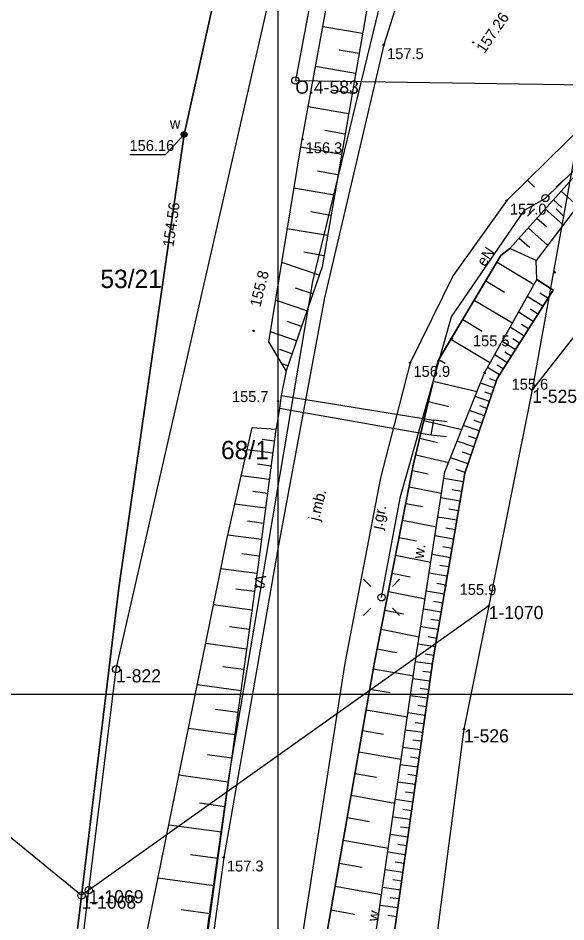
# Model space of a CAD drawing. Extents: x 5598798 to 5599616, y 5661498 to 5662453.
# Drawn here: x 5599182.2 to 5599219.7, y 5661984.4 to 5662046.3 of the extents above; entities that cross this region are included whole.
import ezdxf

# ---------------------------------------------------------------- set-up
doc = ezdxf.new("R2010")
doc.units = 0
for name, color, linetype in [('BUBZ_L_1', 7, 'Continuous'), ('BUIB_L_1', 7, 'Continuous'), ('BUIB_L_4', 7, 'Continuous'), ('Dzialki', 7, 'Continuous'), ('Kontury', 7, 'Continuous'), ('KTJZ_E_T_0', 7, 'Continuous'), ('KTJZ_L_0', 7, 'Continuous'), ('Numery_dzialek', 7, 'Continuous'), ('Numery_punktow', 7, 'Continuous'), ('Podzial_sekcyjny_krzyze', 7, 'Continuous'), ('Podzial_sekcyjny_podstawowy', 7, 'Continuous'), ('PTRW_E_T_1', 7, 'Continuous'), ('PTRW_L_0', 7, 'Continuous'), ('Punkty', 7, 'Continuous'), ('RTPW_T_0', 7, 'Continuous'), ('RTPW_T_1', 7, 'Continuous'), ('SUPE_E_T_3', 7, 'Continuous'), ('SUPE_L_3', 7, 'Continuous'), ('SUPT_E_T_0', 7, 'Continuous'), ('SUPT_L_0', 7, 'Continuous'), ('SUPW_L_0', 7, 'Continuous'), ('SUSM_T_0', 7, 'Continuous'), ('SUTW_T_0', 7, 'Continuous'), ('SUUW_E_T_5', 7, 'Continuous'), ('SUUW_T_7', 7, 'Continuous'), ('Uzytki', 7, 'Continuous')]:
    doc.layers.add(name, color=color, linetype=linetype)

# ---------------------------------------------------------------- blocks, each defined once
blk = doc.blocks.new('GRO')
blk.add_circle((0, 0), 0.045)
blk = doc.blocks.new('GRT')
blk.add_circle((0, 0), 0.25)
blk = doc.blocks.new('POINT_DISPLAY')
blk.add_line((0, 0), (0, 0))
blk = doc.blocks.new('2_RTPW01')
blk.add_circle((0, 0), 0.045)
blk = doc.blocks.new('2_RTPW02')
blk.add_circle((0, 0), 0.045)
blk = doc.blocks.new('4_SUSM01')
for p, q in [((-0.74249, 0.74249), (-1.23746, 1.23746)), ((0.74249, 0.74249), (1.23746, 1.23746)), ((-0.74249, -0.74249), (-1.23746, -1.23746)), ((0.74249, -0.74249), (1.23746, -1.23746))]:
    blk.add_line(p, q)
blk.add_circle((0, 0), 0.245)
blk = doc.blocks.new('4_SUPS01_08')
blk.add_circle((0, 0), 0.0625)
blk = doc.blocks.new('4_SUUS25')
for radius in [0.2, 0.175, 0.15, 0.125, 0.1, 0.075, 0.05, 0.025, 0.00715]:
    blk.add_circle((0, 0), radius)

msp = doc.modelspace()

# ---------------------------------------------------------------- linework, layer by layer
at = {"layer": 'BUBZ_L_1'}
for p, q in [((5599201.547205, 5662037.521709), (5599204.289076, 5662052.472617)), ((5599207.009383, 5662052.339919), (5599203.009868, 5662029.29958)), ((5599205.783558, 5662045.278206), (5599203.056496, 5662045.75159)), ((5599205.546866, 5662043.914675), (5599204.176857, 5662044.152492)), ((5599205.309049, 5662042.544666), (5599202.556014, 5662043.022559)), ((5599205.070103, 5662041.168149), (5599203.687046, 5662041.40823)), ((5599204.830022, 5662039.785092), (5599202.050766, 5662040.267536)), ((5599204.5888, 5662038.395464), (5599203.19257, 5662038.637832)), ((5599215.891937, 5662030.548676), (5599223.373416, 5662038.93789)), ((5599199.359348, 5662024.143271), (5599201.547205, 5662037.521709)), ((5599204.346432, 5662036.999235), (5599201.541391, 5662037.486155)), ((5599204.102972, 5662035.596715), (5599202.707305, 5662035.838985)), ((5599203.860701, 5662034.201048), (5599201.08301, 5662034.683221)), ((5599221.431197, 5662034.656453), (5599217.701626, 5662029.719398)), ((5599219.397499, 5662034.47957), (5599220.532764, 5662033.467144)), ((5599218.869786, 5662033.88783), (5599219.461527, 5662033.360117)), ((5599203.619615, 5662032.812202), (5599202.237557, 5662033.052111)), ((5599218.319661, 5662033.270958), (5599219.553405, 5662032.170708)), ((5599217.746172, 5662032.627887), (5599218.389243, 5662032.054398)), ((5599203.379707, 5662031.430144), (5599200.629098, 5662031.907615)), ((5599217.148327, 5662031.957504), (5599218.489092, 5662030.761813)), ((5599216.52509, 5662031.25865), (5599217.223945, 5662030.635414)), ((5599215.89, 5662030.55), (5599215.28, 5662030.07)), ((5599217.7, 5662029.72), (5599215.89, 5662030.55)), ((5599217.701626, 5662029.719398), (5599215.891937, 5662030.548676)), ((5599203.140971, 5662030.05484), (5599201.772388, 5662030.292409)), ((5599215.28, 5662030.07), (5599210.98, 5662022.88)), ((5599202.806313, 5662028.711306), (5599200.250984, 5662029.595502)), ((5599203.009868, 5662029.29958), (5599200.544989, 5662022.176077)), ((5599215.006929, 5662029.613399), (5599217.480202, 5662028.134251)), ((5599217.73, 5662028.42), (5599217.7, 5662029.72)), ((5599214.16, 5662022.02), (5599217.73, 5662028.42)), ((5599214.235444, 5662028.323406), (5599215.525438, 5662027.551921)), ((5599218.85, 5662027.7), (5599217.724991, 5662028.41102)), ((5599217.73, 5662028.42), (5599218.85, 5662027.7)), ((5599202.364215, 5662027.433642), (5599201.196884, 5662027.837562)), ((5599218.85, 5662027.7), (5599215.02, 5662021.64)), ((5599218.49449, 5662027.137496), (5599217.947415, 5662027.483254)), ((5599201.960294, 5662026.266311), (5599199.827244, 5662027.004391)), ((5599213.452142, 5662027.013652), (5599216.07165, 5662025.447048)), ((5599218.148731, 5662026.590421), (5599217.084594, 5662027.262969)), ((5599217.485406, 5662025.540878), (5599216.478847, 5662026.177037)), ((5599217.812457, 5662026.058352), (5599217.294983, 5662026.385402)), ((5599201.591254, 5662025.199786), (5599200.61683, 5662025.536957)), ((5599212.656841, 5662025.683835), (5599213.986658, 5662024.888534)), ((5599201.254084, 5662024.225362), (5599199.473529, 5662024.841471)), ((5599216.857973, 5662024.548124), (5599215.905876, 5662025.149861)), ((5599217.167327, 5662025.037598), (5599216.677852, 5662025.346953)), ((5599211.849358, 5662024.333647), (5599214.549733, 5662022.718681)), ((5599216.557104, 5662024.072075), (5599216.094113, 5662024.364691)), ((5599200.544989, 5662022.176077), (5599199.359348, 5662024.143271)), ((5599200.946029, 5662023.335085), (5599200.112645, 5662023.623453)), ((5599216.264488, 5662023.609085), (5599215.363907, 5662024.178264)), ((5599215.703115, 5662022.720855), (5599214.851262, 5662023.259238)), ((5599215.979898, 5662023.158794), (5599215.541959, 5662023.435578)), ((5599200.657661, 5662022.501701), (5599200.26733, 5662022.636764)), ((5599210.98, 5662022.88), (5599209.29, 5662015.78)), ((5599211.019573, 5662022.946169), (5599211.449659, 5662022.688954)), ((5599215.172117, 5662021.880686), (5599214.366356, 5662022.389937)), ((5599215.433924, 5662022.294929), (5599215.019681, 5662022.556736)), ((5599211.44, 5662015.25), (5599214.16, 5662022.02)), ((5599210.640276, 5662021.452758), (5599213.644769, 5662020.737604)), ((5599215.02, 5662021.64), (5599212.8, 5662015.14)), ((5599214.804276, 5662021.008376), (5599213.880341, 5662021.323936)), ((5599214.957985, 5662021.458425), (5599214.507936, 5662021.612134)), ((5599214.646496, 5662020.546408), (5599214.172294, 5662020.708367)), ((5599210.307562, 5662020.054963), (5599211.705356, 5662019.722248)), ((5599214.484538, 5662020.072206), (5599213.511017, 5662020.404701)), ((5599214.147641, 5662019.085794), (5599213.121873, 5662019.436133)), ((5599214.318291, 5662019.585446), (5599213.818639, 5662019.756096)), ((5599209.997981, 5662018.754357), (5599212.599192, 5662018.135196)), ((5599213.972471, 5662018.572911), (5599213.446005, 5662018.752719)), ((5599196.49, 5662010.61), (5599198.22, 5662018.29)), ((5599198.22, 5662018.29), (5599199.84, 5662018.16)), ((5599199.84, 5662018.16), (5599198.63, 5662008.86)), ((5599213.792663, 5662018.046445), (5599212.711845, 5662018.415585)), ((5599199.735285, 5662017.355167), (5599198.896923, 5662017.464244)), ((5599209.709925, 5662017.544183), (5599210.9201, 5662017.256127)), ((5599213.608092, 5662017.506036), (5599213.053372, 5662017.695494)), ((5599213.418634, 5662016.951316), (5599212.279812, 5662017.340267)), ((5599199.626208, 5662016.516805), (5599197.871982, 5662016.745043)), ((5599209.441898, 5662016.418152), (5599211.69396, 5662015.882098)), ((5599213.024532, 5662015.797414), (5599211.824593, 5662016.207239)), ((5599213.224158, 5662016.381905), (5599212.639667, 5662016.581531)), ((5599199.512089, 5662015.639692), (5599198.594434, 5662015.759086)), ((5599209.29, 5662015.78), (5599206.61, 5662002.2)), ((5599199.392695, 5662014.722038), (5599197.472555, 5662014.971862)), ((5599209.201512, 5662015.331619), (5599210.293462, 5662015.116124)), ((5599209.49, 5662002.77), (5599211.44, 5662015.25)), ((5599212.8, 5662015.14), (5599210.61, 5662002.29)), ((5599212.819619, 5662015.197444), (5599212.203761, 5662015.407784)), ((5599212.700862, 5662014.558302), (5599211.367431, 5662014.785556)), ((5599199.267783, 5662013.761967), (5599198.263337, 5662013.892654)), ((5599208.981634, 5662014.217459), (5599211.209954, 5662013.777703)), ((5599212.587235, 5662013.891586), (5599211.925123, 5662014.004428)), ((5599208.757283, 5662013.080637), (5599209.894105, 5662012.856287)), ((5599212.474393, 5662013.229474), (5599211.159313, 5662013.4536)), ((5599199.137097, 5662012.757521), (5599197.03535, 5662013.030974)), ((5599212.36233, 5662012.571934), (5599211.70933, 5662012.683223)), ((5599199.00037, 5662011.706648), (5599197.900923, 5662011.849694)), ((5599208.528369, 5662011.920692), (5599210.84826, 5662011.462864)), ((5599212.25104, 5662011.918934), (5599210.954059, 5662012.139976)), ((5599212.140519, 5662011.270443), (5599211.496506, 5662011.380201)), ((5599189.8, 5661977.78), (5599196.49, 5662010.61)), ((5599198.857324, 5662010.607201), (5599196.556794, 5662010.906517)), ((5599208.294799, 5662010.737153), (5599209.478338, 5662010.503583)), ((5599212.030761, 5662010.62643), (5599210.75163, 5662010.84443)), ((5599211.921761, 5662009.986865), (5599211.286612, 5662010.095112)), ((5599198.707666, 5662009.456936), (5599197.513022, 5662009.612368)), ((5599208.056478, 5662009.52954), (5599210.471703, 5662009.052898)), ((5599211.813514, 5662009.351715), (5599210.551987, 5662009.566715)), ((5599198.63, 5662008.86), (5599194.46, 5661978.54)), ((5599211.706014, 5662008.720951), (5599211.079606, 5662008.827709)), ((5599198.547876, 5662008.262875), (5599196.080851, 5662008.602173)), ((5599207.813309, 5662008.297365), (5599209.045485, 5662008.054196)), ((5599211.599257, 5662008.094543), (5599210.355091, 5662008.306584)), ((5599211.493236, 5662007.472461), (5599210.875449, 5662007.577749)), ((5599198.378227, 5662007.029363), (5599197.104972, 5662007.204477)), ((5599207.565194, 5662007.040126), (5599210.079671, 5662006.543897)), ((5599211.387948, 5662006.854673), (5599210.160906, 5662007.063796)), ((5599211.283387, 5662006.241152), (5599210.674102, 5662006.344991)), ((5599198.203112, 5662005.756108), (5599195.574556, 5662006.117621)), ((5599207.312033, 5662005.757315), (5599208.594844, 5662005.504154)), ((5599211.179548, 5662005.631867), (5599209.969392, 5662005.838111)), ((5599211.076426, 5662005.026789), (5599210.475526, 5662005.1292)), ((5599198.022356, 5662004.44183), (5599196.665733, 5662004.62841)), ((5599207.053722, 5662004.448411), (5599209.67153, 5662003.931789)), ((5599210.974015, 5662004.42589), (5599209.780515, 5662004.629296)), ((5599210.872313, 5662003.82914), (5599210.279683, 5662003.93014)), ((5599197.835775, 5662003.085207), (5599195.035112, 5662003.470391)), ((5599210.771312, 5662003.23651), (5599209.594237, 5662003.437117)), ((5599205.3, 5661973.9), (5599209.49, 5662002.77)), ((5599206.789955, 5662003.111862), (5599208.126504, 5662002.848096)), ((5599210.671009, 5662002.647973), (5599210.086535, 5662002.747583)), ((5599206.61, 5662002.2), (5599202.2, 5661977.13)), ((5599210.61, 5662002.29), (5599206.59, 5661973.92)), ((5599210.577764, 5662002.062506), (5599209.411307, 5662002.227791)), ((5599197.643184, 5662001.684875), (5599196.197734, 5662001.883672)), ((5599206.529917, 5662001.744746), (5599209.271216, 5662001.262531)), ((5599210.495121, 5662001.479277), (5599209.910912, 5662001.562059)), ((5599197.444387, 5662000.239426), (5599194.460346, 5662000.64983)), ((5599210.41234, 5662000.895068), (5599209.241954, 5662001.06091)), ((5599206.285137, 5662000.353218), (5599207.676665, 5662000.108438)), ((5599210.329418, 5662000.309875), (5599209.743241, 5662000.392936)), ((5599210.246358, 5661999.723697), (5599209.07203, 5661999.890098)), ((5599197.239185, 5661998.747405), (5599195.699093, 5661998.959219)), ((5599206.036629, 5661998.940494), (5599208.862077, 5661998.443476)), ((5599210.163157, 5661999.136534), (5599209.575005, 5661999.219874)), ((5599210.079817, 5661998.548382), (5599208.901534, 5661998.715344)), ((5599197.027371, 5661997.207314), (5599193.847947, 5661997.644589)), ((5599209.996336, 5661997.959241), (5599209.406203, 5661998.042862)), ((5599205.784334, 5661997.50625), (5599207.218578, 5661997.253956)), ((5599209.912715, 5661997.369108), (5599208.730464, 5661997.536632)), ((5599209.74505, 5661996.185863), (5599208.558817, 5661996.353951)), ((5599209.828953, 5661996.777983), (5599209.236833, 5661996.861886)), ((5599196.808733, 5661995.617601), (5599195.167802, 5661995.843284)), ((5599205.528197, 5661996.050159), (5599208.440379, 5661995.537885)), ((5599209.576821, 5661994.998632), (5599208.386593, 5661995.167286)), ((5599209.661006, 5661995.592747), (5599209.066892, 5661995.676932)), ((5599205.268158, 5661994.571888), (5599206.746429, 5661994.311849)), ((5599209.492494, 5661994.403518), (5599208.896378, 5661994.487987)), ((5599196.583051, 5661993.97667), (5599193.195451, 5661994.442577)), ((5599209.408025, 5661993.807403), (5599208.213788, 5661993.976625)), ((5599209.323414, 5661993.210285), (5599208.725291, 5661993.295038)), ((5599205.004158, 5661993.0711), (5599208.005736, 5661992.5431)), ((5599209.23866, 5661992.612162), (5599208.040401, 5661992.781954)), ((5599196.350098, 5661992.28287), (5599194.601725, 5661992.523329)), ((5599209.153764, 5661992.013032), (5599208.553627, 5661992.098071)), ((5599204.736137, 5661991.54745), (5599206.259787, 5661991.279429)), ((5599209.068725, 5661991.412895), (5599207.866431, 5661991.583259)), ((5599196.109639, 5661990.534497), (5599192.500231, 5661991.030909)), ((5599208.983543, 5661990.811747), (5599208.381385, 5661990.897073)), ((5599208.898218, 5661990.209589), (5599207.691874, 5661990.380526)), ((5599204.464033, 5661990.000592), (5599207.55775, 5661989.456384)), ((5599208.812749, 5661989.606417), (5599208.208562, 5661989.692029)), ((5599195.861433, 5661988.729793), (5599193.998583, 5661988.985996)), ((5599208.727137, 5661989.00223), (5599207.51673, 5661989.173743)), ((5599204.187784, 5661988.43017), (5599205.758205, 5661988.153922)), ((5599208.64138, 5661988.397026), (5599208.035158, 5661988.482927)), ((5599208.555479, 5661987.790805), (5599207.340995, 5661987.962896)), ((5599195.605229, 5661986.866943), (5599191.759491, 5661987.395859)), ((5599208.469433, 5661987.183563), (5599207.86117, 5661987.269753)), ((5599203.907328, 5661986.835828), (5599207.096013, 5661986.274914)), ((5599208.383243, 5661986.575299), (5599207.164669, 5661986.74797)), ((5599208.296908, 5661985.966012), (5599207.686595, 5661986.052493)), ((5599195.340771, 5661984.944074), (5599193.355949, 5661985.217053)), ((5599203.622599, 5661985.217199), (5599205.241227, 5661984.93247)), ((5599208.210427, 5661985.3557), (5599206.987749, 5661985.528952)), ((5599208.123801, 5661984.744361), (5599207.511433, 5661984.831133))]:
    msp.add_line(p, q, dxfattribs=at)
at = {"layer": 'BUIB_L_1'}
for p, q in [((5599200.544989, 5662022.176077), (5599200.203422, 5662020.477517)), ((5599200.203422, 5662020.477517), (5599200.093431, 5662019.594602)), ((5599200.093431, 5662019.594602), (5599199.865493, 5662018.178757)), ((5599210.64656, 5662018.793972), (5599210.479527, 5662017.779699)), ((5599211.579697, 5662018.675115), (5599210.64656, 5662018.793972)), ((5599210.479527, 5662017.779699), (5599211.552657, 5662017.664024))]:
    msp.add_line(p, q, dxfattribs=at)
at = {"layer": 'BUIB_L_4'}
for p, q in [((5599200.203422, 5662020.477517), (5599210.64656, 5662018.793972)), ((5599200.093431, 5662019.594602), (5599210.479527, 5662017.779699))]:
    msp.add_line(p, q, dxfattribs=at)
at = {"layer": 'Dzialki'}
for p, q in [((5599186.52, 5661986.2), (5599074.88, 5662077.34)), ((5599188.89, 5662001.71), (5599201.39, 5662056.39)), ((5599203.66, 5662055.13), (5599201.18, 5662042.06)), ((5599201.18, 5662042.06), (5599221.18, 5662041.76)), ((5599221.18, 5662041.76), (5599217.42, 5662020.87)), ((5599224.84, 5662030.32), (5599217.42, 5662020.87)), ((5599217.42, 5662020.87), (5599214.44, 5662006.05)), ((5599214.44, 5662006.05), (5599187.02, 5661986.57)), ((5599214.44, 5662006.05), (5599212.74, 5661997.6)), ((5599187.02, 5661986.57), (5599188.89, 5662001.71)), ((5599212.74, 5661997.6), (5599207.78, 5661959.89)), ((5599183.8, 5661960.37), (5599187.02, 5661986.57)), ((5599187.02, 5661986.57), (5599186.52, 5661986.2))]:
    msp.add_line(p, q, dxfattribs=at)
at = {"layer": 'Kontury'}
for p, q in [((5599186.52, 5661986.2), (5599074.88, 5662077.34)), ((5599224.84, 5662030.32), (5599217.42, 5662020.87)), ((5599217.42, 5662020.87), (5599214.44, 5662006.05)), ((5599214.44, 5662006.05), (5599212.74, 5661997.6)), ((5599212.74, 5661997.6), (5599207.78, 5661959.89)), ((5599183.8, 5661960.37), (5599187.02, 5661986.57)), ((5599187.02, 5661986.57), (5599186.52, 5661986.2))]:
    msp.add_line(p, q, dxfattribs=at)
at = {"layer": 'KTJZ_L_0'}
for p, q in [((5599208.94, 5662049.84), (5599207.24, 5662044.5)), ((5599207.24, 5662044.5), (5599203.19, 5662027.17)), ((5599221.36, 5662039.44), (5599215.67, 5662033.84)), ((5599215.89, 5662030.55), (5599223.37, 5662038.94)), ((5599215.67, 5662033.84), (5599211.99, 5662028.71)), ((5599215.28, 5662030.07), (5599215.89, 5662030.55)), ((5599210.98, 5662022.88), (5599215.28, 5662030.07)), ((5599211.99, 5662028.71), (5599209.05, 5662022.72)), ((5599203.19, 5662027.17), (5599199.97, 5662009.96)), ((5599209.05, 5662022.72), (5599207.01, 5662014.82)), ((5599209.29, 5662015.78), (5599210.98, 5662022.88)), ((5599206.61, 5662002.2), (5599209.29, 5662015.78)), ((5599207.01, 5662014.82), (5599204.57, 5662002.13)), ((5599199.97, 5662009.96), (5599196.27, 5661988.82)), ((5599204.57, 5662002.13), (5599201.57, 5661982.98)), ((5599202.2, 5661977.13), (5599206.61, 5662002.2)), ((5599196.27, 5661988.82), (5599193.67, 5661969.75))]:
    msp.add_line(p, q, dxfattribs=at)
at = {"layer": 'Podzial_sekcyjny_krzyze'}
for p, q in [((5599200, 5661997.5), (5599200, 5662002.5)), ((5599197.5, 5662000), (5599202.5, 5662000))]:
    msp.add_line(p, q, dxfattribs=at)
at = {"layer": 'Podzial_sekcyjny_podstawowy'}
for p, q in [((5599200, 5662000), (5599200, 5662250)), ((5598800, 5662000), (5599200, 5662000)), ((5599200, 5661750), (5599200, 5662000)), ((5599200, 5662000), (5599600, 5662000))]:
    msp.add_line(p, q, dxfattribs=at)
at = {"layer": 'PTRW_L_0'}
for p, q in [((5599215.89, 5662030.55), (5599215.28, 5662030.07)), ((5599217.7, 5662029.72), (5599215.89, 5662030.55)), ((5599215.28, 5662030.07), (5599210.98, 5662022.88)), ((5599217.73, 5662028.42), (5599217.7, 5662029.72)), ((5599218.85, 5662027.7), (5599217.73, 5662028.42)), ((5599215.02, 5662021.64), (5599218.85, 5662027.7)), ((5599210.98, 5662022.88), (5599209.29, 5662015.78)), ((5599212.8, 5662015.14), (5599215.02, 5662021.64)), ((5599209.29, 5662015.78), (5599206.61, 5662002.2)), ((5599210.61, 5662002.29), (5599212.8, 5662015.14)), ((5599206.61, 5662002.2), (5599202.2, 5661977.13)), ((5599206.59, 5661973.92), (5599210.61, 5662002.29))]:
    msp.add_line(p, q, dxfattribs=at)
at = {"layer": 'SUPE_L_3'}
for p, q in [((5599218.324532, 5662034.005569), (5599224.255584, 5662039.803043)), ((5599216.902559, 5662033.182877), (5599218.324532, 5662034.005569)), ((5599211.896469, 5662025.8657), (5599216.902559, 5662033.182877)), ((5599208.384646, 5662013.550115), (5599211.896469, 5662025.8657)), ((5599207.091102, 5662006.637471), (5599208.384646, 5662013.550115))]:
    msp.add_line(p, q, dxfattribs=at)
at = {"layer": 'SUPT_L_0'}
for p, q in [((5599207.516805, 5662049.527352), (5599202.357147, 5662028.280122)), ((5599202.357147, 5662028.280122), (5599196.624161, 5661994.403918)), ((5599196.624161, 5661994.403918), (5599193.309647, 5661971.20769))]:
    msp.add_line(p, q, dxfattribs=at)
at = {"layer": 'SUPW_L_0'}
for p, q in [((5599193.556349, 5662038.364661), (5599202.403352, 5662078.401046)), ((5599202.403352, 5662078.401046), (5599193.556349, 5662038.364661)), ((5599189.084637, 5662007.286789), (5599193.556349, 5662038.364661)), ((5599193.556349, 5662038.364661), (5599189.084637, 5662007.286789)), ((5599181.036243, 5661940.982154), (5599189.084637, 5662007.286789)), ((5599189.084637, 5662007.286789), (5599181.036243, 5661940.982154))]:
    msp.add_line(p, q, dxfattribs=at)
at = {"layer": 'SUTW_T_0'}
for p in [(5599193.556349, 5662038.364661), (5599189.834289, 5662036.981911)]:
    msp.add_line(p, (5599192.277129, 5662036.981911), dxfattribs=at)
at = {"layer": 'Uzytki'}
for p, q in [((5599186.52, 5661986.2), (5599074.88, 5662077.34)), ((5599188.89, 5662001.71), (5599201.39, 5662056.39)), ((5599203.66, 5662055.13), (5599201.18, 5662042.06)), ((5599201.18, 5662042.06), (5599221.18, 5662041.76)), ((5599224.84, 5662030.32), (5599217.42, 5662020.87)), ((5599217.42, 5662020.87), (5599214.44, 5662006.05)), ((5599214.44, 5662006.05), (5599212.74, 5661997.6)), ((5599187.02, 5661986.57), (5599188.89, 5662001.71)), ((5599212.74, 5661997.6), (5599207.78, 5661959.89)), ((5599183.8, 5661960.37), (5599187.02, 5661986.57)), ((5599187.02, 5661986.57), (5599186.52, 5661986.2))]:
    msp.add_line(p, q, dxfattribs=at)

# ---------------------------------------------------------------- block references
at = {"layer": 'BUBZ_L_1'}
for p in [(5599215.891937, 5662030.548676), (5599199.84, 5662018.16)]:
    msp.add_blockref('POINT_DISPLAY', p, dxfattribs=at)
at = {"layer": 'Punkty'}
for name, p in [('GRT', (5599201.18, 5662042.06)), ('GRO', (5599217.42, 5662020.87)), ('GRO', (5599214.44, 5662006.05)), ('GRT', (5599188.89, 5662001.71)), ('GRO', (5599212.74, 5661997.6)), ('GRT', (5599186.52, 5661986.2)), ('GRT', (5599187.02, 5661986.57))]:
    msp.add_blockref(name, p, dxfattribs=at)
at = {"layer": 'RTPW_T_0', "rotation": -3.0000000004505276e-06}
for p in [(5599207.24, 5662044.5), (5599201.67, 5662038.05), (5599215.67, 5662033.84), (5599209.05, 5662022.72), (5599214.16, 5662022.02), (5599200, 5662020.09), (5599196.27, 5661988.82)]:
    msp.add_blockref('2_RTPW01', p, dxfattribs=at)
at = {"layer": 'RTPW_T_0'}
for p in [(5599218.970659, 5662028.907845), (5599198.316289, 5662024.898096), (5599211.895509, 5662024.384001), (5599211.464978, 5662007.437213)]:
    msp.add_blockref('2_RTPW01', p, dxfattribs=at)
at = {"layer": 'RTPW_T_1'}
msp.add_blockref('2_RTPW02', (5599213.371089, 5662044.679692), dxfattribs=at)
at = {"layer": 'SUSM_T_0'}
for p in [(5599218.324532, 5662034.005569), (5599207.091102, 5662006.637471)]:
    msp.add_blockref('4_SUSM01', p, dxfattribs=at)
at = {"layer": 'SUTW_T_0'}
msp.add_blockref('4_SUPS01_08', (5599193.556349, 5662038.364661), dxfattribs=at)
at = {"layer": 'SUUW_T_7'}
msp.add_blockref('4_SUUS25', (5599193.556349, 5662038.364661), dxfattribs=at)

# ---------------------------------------------------------------- texts
at = {"layer": 'KTJZ_E_T_0'}
for s, rotation, p in [('j.mb.', 76.200012, (5599202.799048, 5662011.837107)), ('j.gr.', 78.799992, (5599207.10454, 5662011.252988))]:
    msp.add_text(s, height=0.75, rotation=rotation, dxfattribs=at).set_placement(p)
at = {"layer": 'Numery_dzialek'}
for s, p in [('53/21', (5599187.811598, 5662027.838917)), ('68/1', (5599196.081311, 5662016.108158))]:
    msp.add_text(s, height=1.26, dxfattribs=at).set_placement(p)
at = {"layer": 'Numery_punktow'}
for s, p in [('O.4-583', (5599201.18, 5662041.16)), ('1-525', (5599217.42, 5662019.97)), ('1-1070', (5599214.44, 5662005.15)), ('1-822', (5599188.89, 5662000.81)), ('1-526', (5599212.74, 5661996.7)), ('1-1069', (5599187.02, 5661985.67)), ('1-1068', (5599186.52, 5661985.3))]:
    msp.add_text(s, height=0.9, dxfattribs=at).set_placement(p)
at = {"layer": 'PTRW_E_T_1'}
for rotation, p in [(82.499987, (5599209.974411, 5662009.260947)), (80.199989, (5599206.847742, 5661984.383874))]:
    msp.add_text('w.', height=0.75, rotation=rotation, dxfattribs=at).set_placement(p)
at = {"layer": 'RTPW_T_0'}
for s, p in [('157.5', (5599207.47, 5662043.53)), ('156.3', (5599201.89, 5662037.08)), ('157.0', (5599215.89, 5662032.87)), ('156.9', (5599209.28, 5662021.75)), ('155.6', (5599216.005834, 5662020.871255)), ('155.7', (5599196.834106, 5662020.025305)), ('157.3', (5599196.49, 5661987.85))]:
    msp.add_text(s, height=0.75, dxfattribs=at).set_placement(p)
for s, rotation, p in [('155.8', 76.315989, (5599198.780732, 5662026.490471)), ('155.5', 359.664941, (5599213.355186, 5662023.853209)), ('155.9', 359.000756, (5599212.439468, 5662006.822836))]:
    msp.add_text(s, height=0.75, rotation=rotation, dxfattribs=at).set_placement(p)
at = {"layer": 'RTPW_T_1'}
msp.add_text('157.26', height=0.75, rotation=55.741983, dxfattribs=at).set_placement((5599214.148144, 5662043.869749))
at = {"layer": 'SUPE_E_T_3'}
msp.add_text('eN', height=0.75, rotation=55.621799, dxfattribs=at).set_placement((5599214.176901, 5662029.253806))
at = {"layer": 'SUPT_E_T_0'}
msp.add_text('tA', height=0.75, rotation=80.39465, dxfattribs=at).set_placement((5599199.033863, 5662007.182864))
at = {"layer": 'SUTW_T_0'}
msp.add_text('156.16', height=0.75, dxfattribs=at).set_placement((5599189.808729, 5662037.231911))
msp.add_text('154.56', height=0.75, rotation=81.812051, dxfattribs=at).set_placement((5599192.821473, 5662030.624312))
at = {"layer": 'SUUW_E_T_5'}
msp.add_text('w', height=0.75, dxfattribs=at).set_placement((5599192.57544, 5662038.763833))

doc.saveas('drawing.dxf')
